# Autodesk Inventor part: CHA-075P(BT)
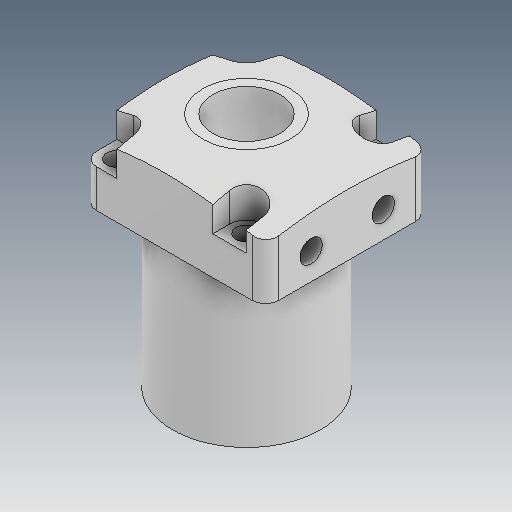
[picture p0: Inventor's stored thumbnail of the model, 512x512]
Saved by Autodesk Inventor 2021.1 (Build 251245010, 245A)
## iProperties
Created: 2021-05
Part Number: CHA-075P(BT)
Material: Ogólny
Document SubType Name: Modeling
Designer: user
Density: 1 g/cm^3
Appearance: Domyślna
Author: user
Revision Number: ÈÎºÎ
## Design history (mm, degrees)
feature "ÇÐ³ý-Ðý×ª1"
node "Bryła1"
